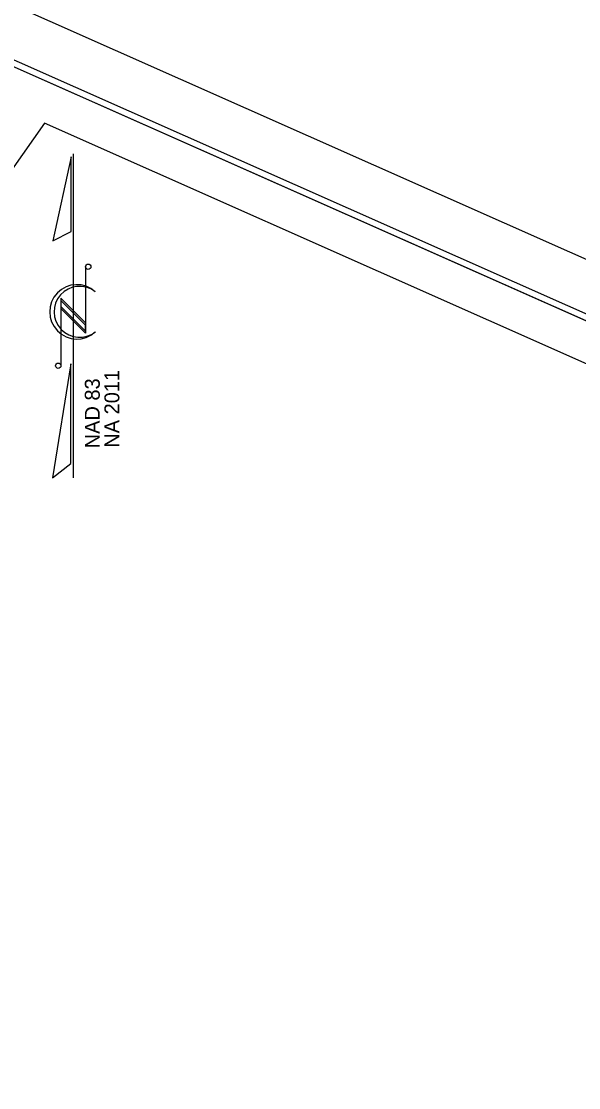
# Model space of a CAD drawing. Extents: x 1637682 to 2864602, y 842496 to 973236.
# Drawn here: x 1639079.8 to 1639303.7, y 843323.7 to 843751.6 of the extents above; entities that cross this region are included whole.
import ezdxf

# ---------------------------------------------------------------- set-up
doc = ezdxf.new("R2010")
doc.units = 0
for name, color, linetype in [('Sheet Clip Boundary CELL', 7, 'Continuous'), ('Sheet North Arrow CELL', 7, 'Continuous'), ('Sheet Plan CELL', 7, 'Continuous'), ('Sheet Plot Border Inside CELL', 7, 'Continuous'), ('Sheet Plot Border Outside CELL', 7, 'Continuous')]:
    doc.layers.add(name, color=color, linetype=linetype)

msp = doc.modelspace()

# ---------------------------------------------------------------- linework, layer by layer
at = {"layer": 'Sheet Clip Boundary CELL'}
msp.add_lwpolyline([(1638095.26, 843695.55), (1638010.34, 843303.19), (1637949.73, 843324.57), (1637886.34, 843167.39), (1638760.91, 842777.56), (1638750.92, 842749.91), (1638861.21, 842700.69), (1639015.67, 842665.82), (1639189.46, 842589.52), (1639522.76, 843341.19), (1639380.4, 843404.31), (1639446.06, 843552.39), (1639089.07, 843710.68), (1638988.3, 843567.43), (1638956.05, 843552.43), (1638629.84, 843695.47), (1638719.07, 843884.38), (1638267, 844086.34)], close=True, dxfattribs=at)
at = {"layer": 'Sheet North Arrow CELL'}
for p, q in [((1639100.72, 843568.39), (1639100.72, 843698.39)), ((1639105.62, 843653.15), (1639105.62, 843626.47)), ((1639109.3, 843643.21), (1639109.44, 843643.11)), ((1639105.62, 843630.63), (1639095.68, 843640.57)), ((1639095.68, 843640.57), (1639095.68, 843613.45)), ((1639105.62, 843629.65), (1639095.68, 843639.59)), ((1639095.68, 843639.59), (1639095.68, 843637.15)), ((1639105.62, 843627.21), (1639095.68, 843637.15)), ((1639095.68, 843637.15), (1639105.62, 843627.21)), ((1639105.62, 843626.47), (1639095.68, 843636.41)), ((1639105.62, 843627.21), (1639105.62, 843629.65))]:
    msp.add_line(p, q, dxfattribs=at)
for points in [[(1639099.82, 843697.25), (1639092.4, 843663.49), (1639099.82, 843667.25)], [(1639099.66, 843614.19), (1639092.3, 843568.39), (1639099.66, 843574.19)]]:
    msp.add_lwpolyline(points, close=True, dxfattribs=at)
for centre in [(1639106.68, 843653.12), (1639094.62, 843613.4)]:
    msp.add_circle(centre, 1.06, dxfattribs=at)
for centre, radius, start, end in [((1639102.11, 843635.01), 10.92, 47.84, 312.3941), ((1639103.16, 843635.02), 10.24, 53.095, 308.6287)]:
    msp.add_arc(centre, radius, start, end, dxfattribs=at)
at = {"layer": 'Sheet Plan CELL'}
for points in [[(1639640.56, 843483.39), (1638269.28, 844091.43), (1637843.67, 843131.56), (1639214.92, 842523.53)], [(1637843.67, 843131.56), (1638269.25, 844091.42), (1639457.67, 843564.51), (1639396.85, 843427.32), (1639579.71, 843346.22), (1639214.92, 842523.53)]]:
    msp.add_lwpolyline(points, close=True, dxfattribs=at)
at = {"layer": 'Sheet Plot Border Inside CELL'}
msp.add_lwpolyline([(1637702.34, 843191.48), (1639225.33, 842516.19), (1639652.97, 843480.61), (1638129.98, 844155.92)], close=True, dxfattribs=at)
at = {"layer": 'Sheet Plot Border Outside CELL'}
msp.add_lwpolyline([(1637682.35, 843178.46), (1639221.34, 842496.06), (1639665.19, 843497.07), (1638126.2, 844179.47)], close=True, dxfattribs=at)
msp.add_lwpolyline([(1637682.35, 843178.46), (1639221.34, 842496.06), (1639665.19, 843497.07), (1638126.2, 844179.47)], close=True, dxfattribs=at)

# ---------------------------------------------------------------- texts
at = {"layer": 'Sheet North Arrow CELL'}
for s, p in [('NAD 83', (1639111.3, 843580.25)), ('NA 2011', (1639119.16, 843580.49))]:
    msp.add_text(s, height=6, rotation=90, dxfattribs=at).set_placement(p)

doc.saveas('drawing.dxf')
